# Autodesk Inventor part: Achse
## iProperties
Created: 2003-12
Part Number: Achse
Material: Standard
Document SubType Name: Modellieren
Designer: Ulrich
Control State: 0
Master: False
Checked Out: False
Shininess: 20.0
Angle Display Precision: 2
Document Length Units: 11269
Document Angle Units: 11279
Document Time Units: 11290
Document Mass Units: 11283
Document Length Units Precision: 3
Document Angle Units Precision: 2
d1: 3,000 mm
Density: 0.0
Volumn: 0.0
Area: 0.0
PropertySet Name: Model Information
Author: Ulrich
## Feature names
1. Drehung1 [Revolution]
